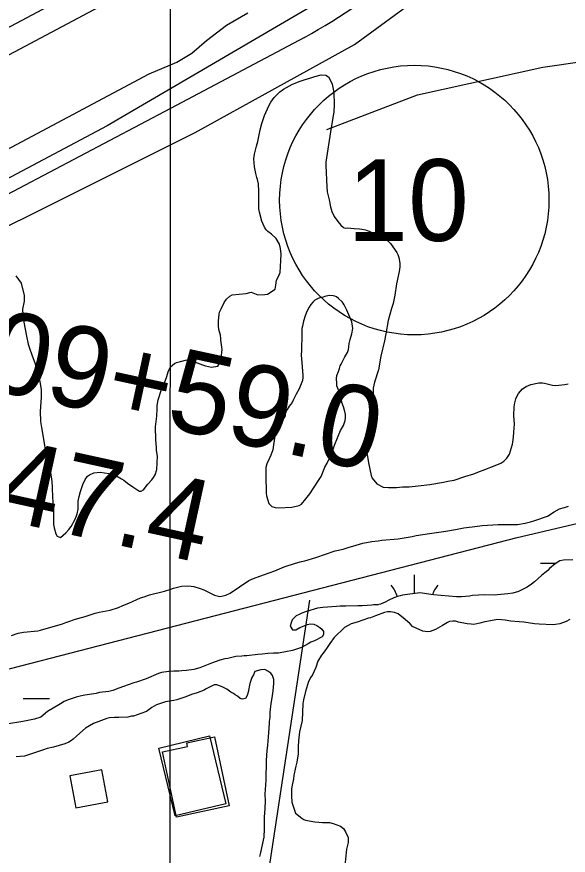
# Model space of a CAD drawing. Extents: x 3245246 to 3283090, y 806824 to 832173.
# Drawn here: x 3259701 to 3260377, y 817056 to 818083 of the extents above; entities that cross this region are included whole.
import ezdxf

# ---------------------------------------------------------------- set-up
doc = ezdxf.new("R2010")
doc.units = 0
for name, color, linetype in [('V-BLDG-OTLN', 7, 'Continuous'), ('V-GRID-MAJR', 7, 'Continuous'), ('V-LEVE-TOET', 7, 'Continuous'), ('V-ROAD-CNTR', 7, 'Continuous'), ('V-ROAD-IDEN', 7, 'Continuous'), ('V-SITE-VEGE', 7, 'Continuous'), ('V-SURV-IDEN', 7, 'Continuous'), ('V-SURV-LINE', 7, 'Continuous'), ('V-TOPO-SHOR', 7, 'Continuous'), ('V-WETL-SWMP', 7, 'Continuous')]:
    doc.layers.add(name, color=color, linetype=linetype)

msp = doc.modelspace()

# ---------------------------------------------------------------- linework, layer by layer
at = {"layer": 'V-BLDG-OTLN'}
for points in [[(3259937.6, 817202.4), (3259957.6, 817119.2), (3259895.6, 817104.3), (3259875.6, 817187.4)], [(3259897.2, 817102.9), (3259880, 817182.8), (3259910.7, 817189.4), (3259909.7, 817194), (3259943.5, 817201.2), (3259961.6, 817116.7)], [(3259766.2, 817153.5), (3259773.6, 817114.2), (3259812.9, 817121.5), (3259805.5, 817160.8)]]:
    msp.add_lwpolyline(points, close=True, dxfattribs=at)
at = {"layer": 'V-GRID-MAJR'}
msp.add_spline([(3259886.4, 812208.7), (3259889.9, 818267.9), (3259893.4, 824330.1), (3259897, 830392.4), (3259897, 830395.5)], degree=3, dxfattribs=at)
at = {"layer": 'V-LEVE-TOET'}
msp.add_lwpolyline([(3259139.6, 817590.7), (3259225.1, 817663.9), (3259298.4, 817711.9), (3259469.9, 817796.8), (3259663.9, 817906.9), (3259863.5, 818012.7), (3259897.5, 818027), (3259915.9, 818038.3), (3259933.7, 818053.8), (3259958.5, 818072.4), (3259984.6, 818087.4)], dxfattribs=at)
at = {"layer": 'V-ROAD-CNTR'}
msp.add_lwpolyline([(3260054.1, 818057.4), (3259889.8, 817970.3), (3259443.4, 817735.3)], dxfattribs=at)
msp.add_arc((3259512.3, 819009.7), 1095.7, 299.6371, 315.8206, dxfattribs=at)
at = {"layer": 'V-ROAD-IDEN'}
msp.add_circle((3260188.5, 817858.3), 165, dxfattribs=at)
msp.add_circle((3260188.5, 817858.3), 165, dxfattribs=at)
at = {"layer": 'V-SITE-VEGE'}
for points in [[(3259962.4, 817740.8), (3259965.3, 817742.2), (3259973.7, 817743.1), (3259982.3, 817743.8), (3259986.8, 817745.1), (3259988.8, 817745.6), (3259996.6, 817742.4), (3260005.3, 817742.5), (3260008.5, 817743.3), (3260017.9, 817749.2), (3260018.9, 817754.1), (3260019.8, 817760.3), (3260021.8, 817763.8), (3260024.2, 817769.5), (3260025.1, 817784.3), (3260025.2, 817792.1), (3260024.7, 817799.1), (3260023.4, 817804.4), (3260019.2, 817811.3), (3260013.7, 817816.4), (3260008.9, 817819.8), (3260007, 817821.8), (3260004.9, 817825.3), (3260001.8, 817832.4), (3259999, 817843.3), (3259998.1, 817847.6), (3259998.1, 817852.1), (3259997.8, 817858.6), (3259997.9, 817868.7), (3259997.6, 817878.3), (3259996.3, 817883.4), (3259995.4, 817886.1), (3259994.4, 817890.8), (3259992.8, 817899), (3259991.7, 817908.6), (3259992.5, 817914.6), (3259995, 817924.4), (3259996.8, 817930), (3259999.7, 817944.2), (3260001.5, 817952), (3260003.5, 817956.9), (3260004.8, 817961.7), (3260010.2, 817973.8), (3260012.9, 817978.2), (3260016.9, 817983.7), (3260021.2, 817988.3), (3260023.8, 817990.8), (3260028.1, 817994.1), (3260039.3, 818000.2), (3260044.6, 818002.1), (3260047.4, 818003.4), (3260053.4, 818005.5), (3260061.9, 818008), (3260066.6, 818009.7), (3260074.2, 818011.5), (3260080.2, 818011.1), (3260083.3, 818009.1), (3260086, 818004.6), (3260087.7, 818000.1), (3260090, 817989.9), (3260090.4, 817975.1), (3260089.7, 817966.1), (3260088.7, 817959.5), (3260085.7, 817941.7), (3260080.3, 817904.7), (3260080.2, 817900.8), (3260081.5, 817874.4), (3260081.6, 817868.4), (3260084.1, 817858.4), (3260085.9, 817850), (3260087.4, 817844.5), (3260090.5, 817838), (3260094.9, 817832.1), (3260098.4, 817827.6), (3260101.9, 817824.8), (3260103.8, 817824), (3260106.7, 817824.2), (3260114.7, 817823.7), (3260121.2, 817823.1), (3260124.1, 817822.7), (3260128.8, 817821.8), (3260130.7, 817821), (3260133.4, 817820.2), (3260136.3, 817818.8), (3260145.1, 817815), (3260147, 817814), (3260150.3, 817812.8), (3260155.6, 817809), (3260159.2, 817805.3), (3260167.1, 817794.1), (3260168.3, 817791.5), (3260169.6, 817787.8), (3260170.7, 817781.2), (3260170.8, 817776.7), (3260169.8, 817771), (3260166.5, 817755.8), (3260164.6, 817742), (3260162.5, 817731.5), (3260160.5, 817725.5), (3260156.5, 817710.7), (3260153.8, 817694.7)], [(3259700.1, 817765.7), (3259706.9, 817756.7), (3259710.6, 817741.4), (3259710.3, 817734.6), (3259708.3, 817724.6), (3259708.6, 817717.6), (3259709.9, 817709), (3259713.4, 817691.8)], [(3259713.4, 817691.8), (3259715.4, 817681.8), (3259716.9, 817676.9), (3259720, 817668.9), (3259723.8, 817657.7), (3259728.1, 817642.6), (3259728.8, 817639.3), (3259729.8, 817635.8), (3259731.2, 817626.2), (3259731.4, 817622.9), (3259731.3, 817616.4), (3259730, 817599.9), (3259730.6, 817587.4), (3259731.7, 817579.9), (3259734.3, 817565.7), (3259737, 817547.5), (3259740, 817534.2), (3259742.6, 817524.8), (3259744.5, 817513.8), (3259744.8, 817506.6), (3259745, 817494.3), (3259745.6, 817489.4), (3259746.4, 817477.5), (3259746.3, 817469.1), (3259746.4, 817461.1), (3259747, 817457), (3259749.4, 817449.6), (3259750.8, 817446.8), (3259754.9, 817445.4), (3259761.6, 817450.8), (3259765.3, 817454.9), (3259768.1, 817458.5), (3259772.7, 817466.9), (3259774.7, 817471.9), (3259775.5, 817474.1), (3259776.5, 817479.9), (3259776.4, 817484.8), (3259776.8, 817489.5), (3259778, 817495.5), (3259779.3, 817501.4), (3259782.5, 817510.1), (3259785.1, 817516.1), (3259787.9, 817520.4), (3259790.4, 817522.1), (3259795.7, 817524.2), (3259803.5, 817525.3), (3259814.1, 817523.6), (3259817.2, 817523), (3259823.4, 817520.8), (3259829.8, 817517.2), (3259832.5, 817515.4), (3259837, 817511.9), (3259843.6, 817507.3), (3259849.6, 817503.3), (3259851.9, 817502.1), (3259854, 817501.9), (3259856.8, 817503.5), (3259861.9, 817510.4), (3259866.7, 817515.6), (3259868.9, 817518.7), (3259870.8, 817522), (3259872.9, 817528.3), (3259873.8, 817544.7), (3259872.5, 817551.9), (3259872.4, 817555.4), (3259871.7, 817564.8), (3259871.5, 817580.6), (3259873, 817593.7), (3259873.3, 817602.8), (3259873.5, 817606.9), (3259874.6, 817613.7), (3259878.2, 817625.2), (3259882.6, 817634.7), (3259885.2, 817642.5), (3259886.8, 817648), (3259889.6, 817654), (3259894.6, 817658.4), (3259896.9, 817659.4), (3259902.2, 817660.7), (3259909.8, 817662.7), (3259914.3, 817661.5), (3259922.5, 817658.9), (3259928.9, 817656.5), (3259932.6, 817655.3), (3259940, 817653.6), (3259947.6, 817655.1), (3259949, 817656.9), (3259951.8, 817664.6), (3259953.1, 817675.2), (3259951.5, 817686.9), (3259951.5, 817689), (3259950.9, 817693.1), (3259949.1, 817700), (3259948.7, 817704.5), (3259948.6, 817710.2), (3259949.3, 817718.5), (3259949.9, 817720.9), (3259951.7, 817725.3), (3259955.5, 817732.7), (3259958.4, 817737), (3259962.4, 817740.8)], [(3260039.9, 817613.3), (3260038.9, 817610.6), (3260036.9, 817608.1), (3260035.3, 817605.8), (3260032.9, 817602.1), (3260030.9, 817598.6), (3260030.3, 817596.5), (3260030.1, 817594.1), (3260029.1, 817591.4), (3260027.3, 817589.9), (3260022.3, 817577.8), (3260020.9, 817576.3), (3260018.2, 817572), (3260016.1, 817558.6), (3260015, 817552.5), (3260012.8, 817545.9), (3260010.8, 817541.4), (3260007.8, 817535.2), (3260006.6, 817531.1), (3260006.5, 817525.3), (3260006.6, 817513.2), (3260007.1, 817507.1), (3260007, 817499.5), (3260007.2, 817496.2), (3260010.2, 817486.8), (3260012.5, 817484.2), (3260014.1, 817483), (3260018.2, 817481.8), (3260022.7, 817481.4), (3260038.3, 817482.2), (3260047.3, 817484.2), (3260050.4, 817486), (3260055.4, 817492.6), (3260060.5, 817498.7), (3260071.2, 817514.8), (3260074.2, 817519.9), (3260079, 817531.3), (3260081.8, 817536.2), (3260086.8, 817546.9), (3260088.2, 817551.7), (3260089.4, 817554.3), (3260090.6, 817558.3), (3260098, 817576), (3260101.6, 817582.4), (3260103.8, 817588.3), (3260104.2, 817591.4), (3260104.1, 817595.9), (3260103.4, 817599.6), (3260101.7, 817605.1), (3260099.8, 817610.6), (3260099.2, 817614.1), (3260097.7, 817620.5), (3260093.7, 817630.9), (3260093.6, 817633.8), (3260093.1, 817639.9), (3260093.5, 817643.4), (3260095.7, 817648.3), (3260096.7, 817652), (3260097.5, 817655.3), (3260098.7, 817657.6), (3260100.5, 817660.7), (3260103.5, 817666.5), (3260106.5, 817671.8), (3260107.9, 817675.3), (3260108.3, 817678.6), (3260108.7, 817682.7), (3260109.8, 817687.7), (3260112, 817694.4), (3260113, 817701), (3260112.9, 817704.1), (3260112.1, 817709.4), (3260108.3, 817717.8), (3260105.7, 817723.7), (3260102.6, 817730.2), (3260101.5, 817732.1), (3260100.1, 817733.9), (3260095.5, 817737.9), (3260093.3, 817739.8), (3260091.2, 817740.6), (3260089.1, 817740.9), (3260084, 817741.3), (3260078.9, 817740.2), (3260076.9, 817739.4), (3260074, 817738.9), (3260071.5, 817738.3), (3260066.6, 817735.8), (3260064.4, 817733.7), (3260061.8, 817730.4), (3260059.8, 817727.1), (3260057, 817721.7), (3260054.6, 817716.4), (3260052.6, 817710), (3260051.4, 817704), (3260050.8, 817700.9), (3260050.5, 817695.4), (3260050.7, 817690.9), (3260050.3, 817677.8), (3260050.3, 817674.5), (3260050, 817668.5), (3260050.7, 817659.3), (3260052.1, 817643.5)], [(3260153.8, 817694.7), (3260151.9, 817685.9), (3260147.4, 817667), (3260144.5, 817650.5), (3260139.7, 817635.5), (3260138.2, 817627.9), (3260138.2, 817608), (3260137.4, 817603.5), (3260136.1, 817593.2), (3260133.6, 817579), (3260131.6, 817571.8), (3260131.1, 817568.8), (3260129.1, 817556.4), (3260129.2, 817553.8), (3260131.3, 817544.2), (3260132.4, 817536.8), (3260135.5, 817521), (3260136.8, 817517.8), (3260142.8, 817511.1), (3260150.4, 817506.8), (3260157, 817506.3), (3260166.8, 817506.4), (3260174, 817507.1), (3260182.2, 817507.2), (3260193.1, 817508.3), (3260207.6, 817510.1), (3260224.4, 817513), (3260229.7, 817514.1), (3260237.5, 817515.2), (3260250.5, 817519.9), (3260261.4, 817523.3), (3260268.5, 817526), (3260273, 817527.5), (3260289.8, 817534), (3260294.7, 817536.3), (3260298.1, 817538.6), (3260302, 817542.4), (3260305, 817547.1), (3260308.7, 817559.5), (3260309.3, 817561.9), (3260309.9, 817568.1), (3260310.6, 817574.3), (3260311.1, 817584.1), (3260310.6, 817594.4)], [(3260052.1, 817643.5), (3260052.1, 817640.9), (3260051.6, 817637.4), (3260047.4, 817627.1), (3260043.9, 817620.7), (3260039.9, 817613.3)], [(3260310.6, 817594.4), (3260310.7, 817605.2), (3260311.9, 817610.2), (3260312.8, 817614.9), (3260314, 817617.8), (3260316.3, 817621.3), (3260320.9, 817627.1), (3260325.4, 817630.2), (3260331.3, 817632.7), (3260341.3, 817634.7), (3260345.8, 817634.5), (3260347.9, 817634.1), (3260358, 817631.8), (3260361.1, 817631.4), (3260365.8, 817631.7), (3260372.9, 817632.4), (3260377.2, 817633.4)], [(3260379.2, 817344.7), (3260374.6, 817342.4), (3260366.8, 817339.7), (3260361.7, 817338.6), (3260358.2, 817338.4), (3260341.6, 817339.2), (3260335.8, 817339.5), (3260322.9, 817341.4), (3260317.1, 817341.8), (3260306.7, 817342.9), (3260299.7, 817343.9), (3260290.7, 817345), (3260274.9, 817341.9), (3260269, 817340.2), (3260265.1, 817339.4), (3260261.6, 817338.9), (3260258.3, 817339.1), (3260253.2, 817339.6), (3260242.7, 817341.6), (3260239, 817342.6), (3260235.7, 817342.9), (3260231.8, 817342.5), (3260229.2, 817341.2), (3260223.1, 817337.5), (3260214.5, 817332.6), (3260208, 817330.1), (3260204.5, 817329.9), (3260198.9, 817330.6), (3260195.4, 817332), (3260186.2, 817336.2), (3260183.3, 817339.5), (3260177.5, 817344.7), (3260168.8, 817351.8), (3260164.4, 817353.4), (3260159.5, 817354), (3260155.8, 817354.1), (3260151.9, 817353.3), (3260141.1, 817349.2), (3260135, 817346.9), (3260132.5, 817346.5), (3260118.4, 817341.4), (3260111.3, 817339.5), (3260108.4, 817338), (3260103.1, 817335.1), (3260090.4, 817322.6), (3260085.1, 817315.6), (3260080.9, 817309.2), (3260077, 817303.8), (3260074.8, 817301.1), (3260070.4, 817293.9), (3260067.8, 817285.9)], [(3260000.6, 817283.3), (3259993.2, 817281.2), (3259991.6, 817277.2), (3259989.6, 817273.7), (3259986.8, 817266.3), (3259985.1, 817255.8), (3259983.9, 817251.9), (3259981.7, 817248), (3259977.4, 817247.3), (3259975.1, 817248.3), (3259971.8, 817250.8), (3259969.1, 817252.4), (3259966.9, 817254.2), (3259963.8, 817256), (3259958.6, 817259.4), (3259953.2, 817262.2), (3259946.4, 817264.8), (3259943.4, 817264.8), (3259932.8, 817259.6), (3259930.9, 817258.5), (3259922.6, 817255.1), (3259915.6, 817252.8), (3259908.5, 817250.1), (3259897.4, 817246.4), (3259894, 817245.6), (3259890.9, 817245.3), (3259883.7, 817244.2), (3259872.7, 817240.2), (3259867, 817237.1), (3259860.5, 817232.3), (3259853.5, 817229.8), (3259844.5, 817226.6), (3259841.9, 817226.3), (3259837.6, 817225.1), (3259826.5, 817224.7), (3259821, 817224.9), (3259814.8, 817224.6), (3259811.6, 817223.7), (3259795.4, 817217.4), (3259785.4, 817211.8), (3259775.1, 817202.2), (3259770.4, 817198.3), (3259768.6, 817196.6), (3259765.3, 817194.5), (3259760.2, 817192.4), (3259746.3, 817188.4), (3259738.8, 817186.8), (3259734.1, 817185.4), (3259722, 817181.1), (3259710.8, 817177.7), (3259705.7, 817177), (3259700.7, 817176.8)], [(3259999.4, 817054.6), (3260000.6, 817059.4), (3260004.5, 817078.3), (3260005, 817088.7), (3260004.9, 817102.9), (3260005.2, 817108), (3260005.8, 817113.6), (3260006.3, 817123), (3260005.6, 817131), (3260007, 817148.2), (3260007.4, 817172), (3260008.2, 817184.3), (3260009, 817190.7), (3260009.3, 817196.4), (3260010.3, 817205.9), (3260011.1, 817217.8), (3260011.1, 817220), (3260011.7, 817225), (3260012, 817231.3), (3260012.4, 817235.2), (3260013.3, 817241.4), (3260014.7, 817251.7), (3260015.6, 817257.6), (3260016.5, 817266.4), (3260016.3, 817271.4), (3260014.8, 817276.3), (3260012.5, 817279.3), (3260009, 817281.7), (3260005.5, 817283.7), (3260000.6, 817283.3)], [(3260067.8, 817285.9), (3260063.6, 817277.2), (3260061.8, 817274.3), (3260058.8, 817269), (3260055.2, 817256.8), (3260052.7, 817246.3), (3260052.1, 817241.4), (3260051.1, 817221.3), (3260048, 817207.3), (3260046.7, 817196.4), (3260046.3, 817189.5), (3260046.2, 817180.2), (3260044.7, 817170.2), (3260043.1, 817163.8), (3260041, 817153.7), (3260040.4, 817149.8), (3260038.7, 817141.8), (3260038.1, 817137.5), (3260037.9, 817134.8), (3260038.2, 817129.1), (3260038.3, 817121.1), (3260043.1, 817107.8), (3260050.6, 817101.8), (3260053.3, 817099.9), (3260055.3, 817099.1), (3260066.6, 817097.2), (3260071.6, 817096.9), (3260075.9, 817096.5), (3260084.5, 817096.2), (3260089.2, 817095.2), (3260098.1, 817092), (3260101.8, 817088.8), (3260104.3, 817084.7), (3260107.3, 817077.8), (3260107.3, 817072), (3260105.4, 817063.6), (3260103.3, 817043.3)]]:
    msp.add_lwpolyline(points, dxfattribs=at)
at = {"layer": 'V-SURV-LINE'}
for points in [[(3259238.3, 817829.2), (3260394.8, 818443.8)], [(3260408.9, 818417.3), (3259252.3, 817802.7)]]:
    msp.add_lwpolyline(points, dxfattribs=at)
at = {"layer": 'V-TOPO-SHOR'}
for points in [[(3259712.4, 817837.2), (3259920, 817940.9), (3260115.2, 818048.7), (3260239.7, 818140), (3260285.4, 818181.5), (3260331.1, 818189.7), (3260389.2, 818185.6), (3260447.3, 818164.8), (3260513.7, 818160.6), (3260571.8, 818168.9), (3260679.7, 818193.7), (3260858.2, 818243.5), (3261231.8, 818355.4)], [(3260152.6, 818148.3), (3259812.1, 817949.2), (3259413.6, 817737.7), (3259264.1, 817646.5), (3259201.8, 817596.7), (3259035.7, 817443.2), (3258545.8, 817011.7), (3258321.5, 816825.1), (3257956.1, 816493.2), (3257545.1, 816115.6), (3257225.3, 815833.5), (3257084.2, 815704.9), (3257013.6, 815651), (3256897.3, 815568), (3256357.6, 815240.4)], [(3260081.5, 817944.6), (3260192.5, 817987.2), (3260346, 818021.2), (3260819.6, 818089.3), (3260981.5, 818115.8)], [(3259106.3, 817434.9), (3259243.3, 817567.6), (3259338.8, 817638.1), (3259417.7, 817692.1), (3259600.4, 817783.3), (3259712.4, 817837.2)], [(3259157.6, 817146.5), (3260314.5, 817445.1), (3260992.7, 817604.4)], [(3260059.9, 817368.6), (3259876, 816152.9), (3259850.3, 815952.4), (3259721.9, 815009.6)]]:
    msp.add_lwpolyline(points, dxfattribs=at)
at = {"layer": 'V-WETL-SWMP'}
for p, q in [((3260343.3, 817413.9), (3260362.4, 817413.9)), ((3260188.7, 817376.5), (3260188.7, 817399.3)), ((3260138.7, 817363.3), (3260144.8, 817363.3)), ((3259709.3, 817248), (3259741.3, 817248))]:
    msp.add_line(p, q, dxfattribs=at)
for points in [[(3260144.2, 817441.2), (3260148.7, 817441.8), (3260168.6, 817443.5), (3260185.7, 817446.4), (3260190.7, 817447.6), (3260207.2, 817450.3), (3260227.1, 817453), (3260238.8, 817455), (3260249.2, 817456.9), (3260266, 817459.2), (3260271.7, 817459.8), (3260291.4, 817461.3), (3260299.4, 817461.2), (3260314.8, 817461.3), (3260324.4, 817462.7), (3260330.7, 817464.2), (3260336.2, 817465.9), (3260351.8, 817471.4), (3260360.1, 817476.6), (3260366.6, 817480.2), (3260372.4, 817482.1), (3260377.5, 817483.6)], [(3259694.8, 817325.4), (3259703.1, 817328), (3259709.7, 817329.5), (3259727.3, 817330.9), (3259730.6, 817331.7), (3259757.6, 817339.6), (3259761.4, 817341.1), (3259767.6, 817343), (3259771.8, 817344.7), (3259785.1, 817348.6), (3259797.4, 817352.6), (3259802.3, 817353.7), (3259815.8, 817356.1), (3259826, 817359.7), (3259831.5, 817362), (3259838.7, 817364.7), (3259853, 817371.3), (3259857.3, 817372.5), (3259864, 817374.9), (3259882.6, 817379.6), (3259890.2, 817381.9), (3259893.6, 817383.2), (3259903.4, 817385.6), (3259910.8, 817386.1), (3259914.9, 817385.7), (3259918.4, 817385.1), (3259926.2, 817382.7), (3259930.6, 817381.2), (3259943.6, 817374.7), (3259950.1, 817373), (3259954.4, 817373.6), (3259957.7, 817374.7), (3259962.8, 817377.2), (3259985.6, 817392.4), (3259991.5, 817395), (3260003.6, 817399.6), (3260017.5, 817404.3), (3260029.1, 817409.3), (3260042.8, 817413.8), (3260050.1, 817415.7), (3260054.2, 817416.6), (3260067.7, 817420.6), (3260091.4, 817428.7), (3260101.4, 817430.9), (3260107.6, 817433), (3260117.2, 817436), (3260125.6, 817438.1), (3260136.6, 817440.5), (3260144.2, 817441.2)], [(3260382.7, 817418), (3260371.4, 817417.5), (3260366.7, 817416.8), (3260361, 817413.1), (3260354.3, 817407.2), (3260352.1, 817405), (3260348.4, 817401.8), (3260344.2, 817398.5), (3260335.9, 817390.8), (3260332.2, 817387.9), (3260326.7, 817384.2), (3260316.3, 817379.3), (3260309.4, 817377), (3260303.2, 817376.1), (3260290.5, 817374.9), (3260287.4, 817374.5), (3260274.5, 817375.2), (3260260, 817374.2), (3260256.3, 817373.5), (3260246.5, 817372.6), (3260240.1, 817372.7), (3260212, 817374.9), (3260208.7, 817375.3), (3260201.1, 817376.8), (3260195.1, 817377.4), (3260174, 817374.5), (3260171, 817373.6), (3260167.9, 817373), (3260163.6, 817371.5), (3260157.1, 817368.5), (3260152.8, 817366.2), (3260146.9, 817363.7), (3260142.4, 817362.8), (3260124.8, 817361.6), (3260119.2, 817361.5), (3260104.7, 817361), (3260097.5, 817361.1), (3260093.2, 817360.6), (3260076.4, 817359.4), (3260069.9, 817358.5), (3260065.6, 817357.5), (3260055.3, 817354.3), (3260050.6, 817352.6), (3260047.4, 817351.1), (3260043.9, 817349.2), (3260039, 817344.4), (3260037.6, 817340.7), (3260036.5, 817336.6), (3260039.2, 817332.3), (3260043.3, 817332.2), (3260048.2, 817334.9), (3260057.8, 817338.9), (3260060.8, 817339.6), (3260065.4, 817339), (3260068.9, 817337.6), (3260072.8, 817335), (3260075.3, 817333), (3260077.3, 817330.3), (3260077.2, 817326.4)], [(3260077.2, 817326.4), (3260075.8, 817323.7), (3260066.4, 817318.9), (3260061.9, 817317), (3260058.4, 817314.9), (3260050.1, 817310.5), (3260039.3, 817306.9), (3260030.7, 817305.2), (3260021.9, 817303.6), (3260015.9, 817303.4), (3260009, 817303.3), (3260002.2, 817302.4), (3259996.7, 817301.9), (3259983.4, 817300.3), (3259980.1, 817300.3), (3259977, 817299.9), (3259970, 817299.4), (3259960, 817297.2), (3259956.5, 817296.8), (3259950.4, 817295.1), (3259939.8, 817291.2), (3259925.7, 817285.5), (3259918.3, 817283.8), (3259909.5, 817282.3), (3259903.6, 817282), (3259900.1, 817281.6), (3259893.7, 817281.5), (3259887.6, 817281.2), (3259878.8, 817279.9), (3259875.1, 817278.6), (3259859.8, 817272.3), (3259848.2, 817268.1), (3259844.9, 817267.2), (3259838, 817264.9), (3259826.5, 817260.6), (3259819.2, 817258.1), (3259814.3, 817256.8), (3259802.8, 817255.5), (3259798.5, 817254.4), (3259784.8, 817252.2), (3259780.5, 817251.3), (3259774.1, 817249.6), (3259764.5, 817246.6), (3259759.4, 817244.5), (3259754.8, 817241.6), (3259738.9, 817232.2), (3259730.7, 817225.3), (3259723.2, 817222.6), (3259708.9, 817220), (3259688.6, 817216.7)]]:
    msp.add_lwpolyline(points, dxfattribs=at)
for centre, start, end in [((3260133.5, 817363.8), 14.8855, 40.7468), ((3260244, 817363.7), 139.2032, 161.2626)]:
    msp.add_arc(centre, 35.2, start, end, dxfattribs=at)

# ---------------------------------------------------------------- texts
at = {"layer": 'V-ROAD-IDEN'}
msp.add_text('10', height=100, rotation=0, dxfattribs=at).set_placement((3260106.6, 817808.3))
at = {"layer": 'V-SURV-IDEN'}
for s, rotation, p in [('2109+59.0', 347.8062, (3259514.6, 817659.8)), ('2108+47.4', 347.6335, (3259305.8, 817549.8))]:
    msp.add_text(s, height=100, rotation=rotation, dxfattribs=at).set_placement(p)

doc.saveas('drawing.dxf')
